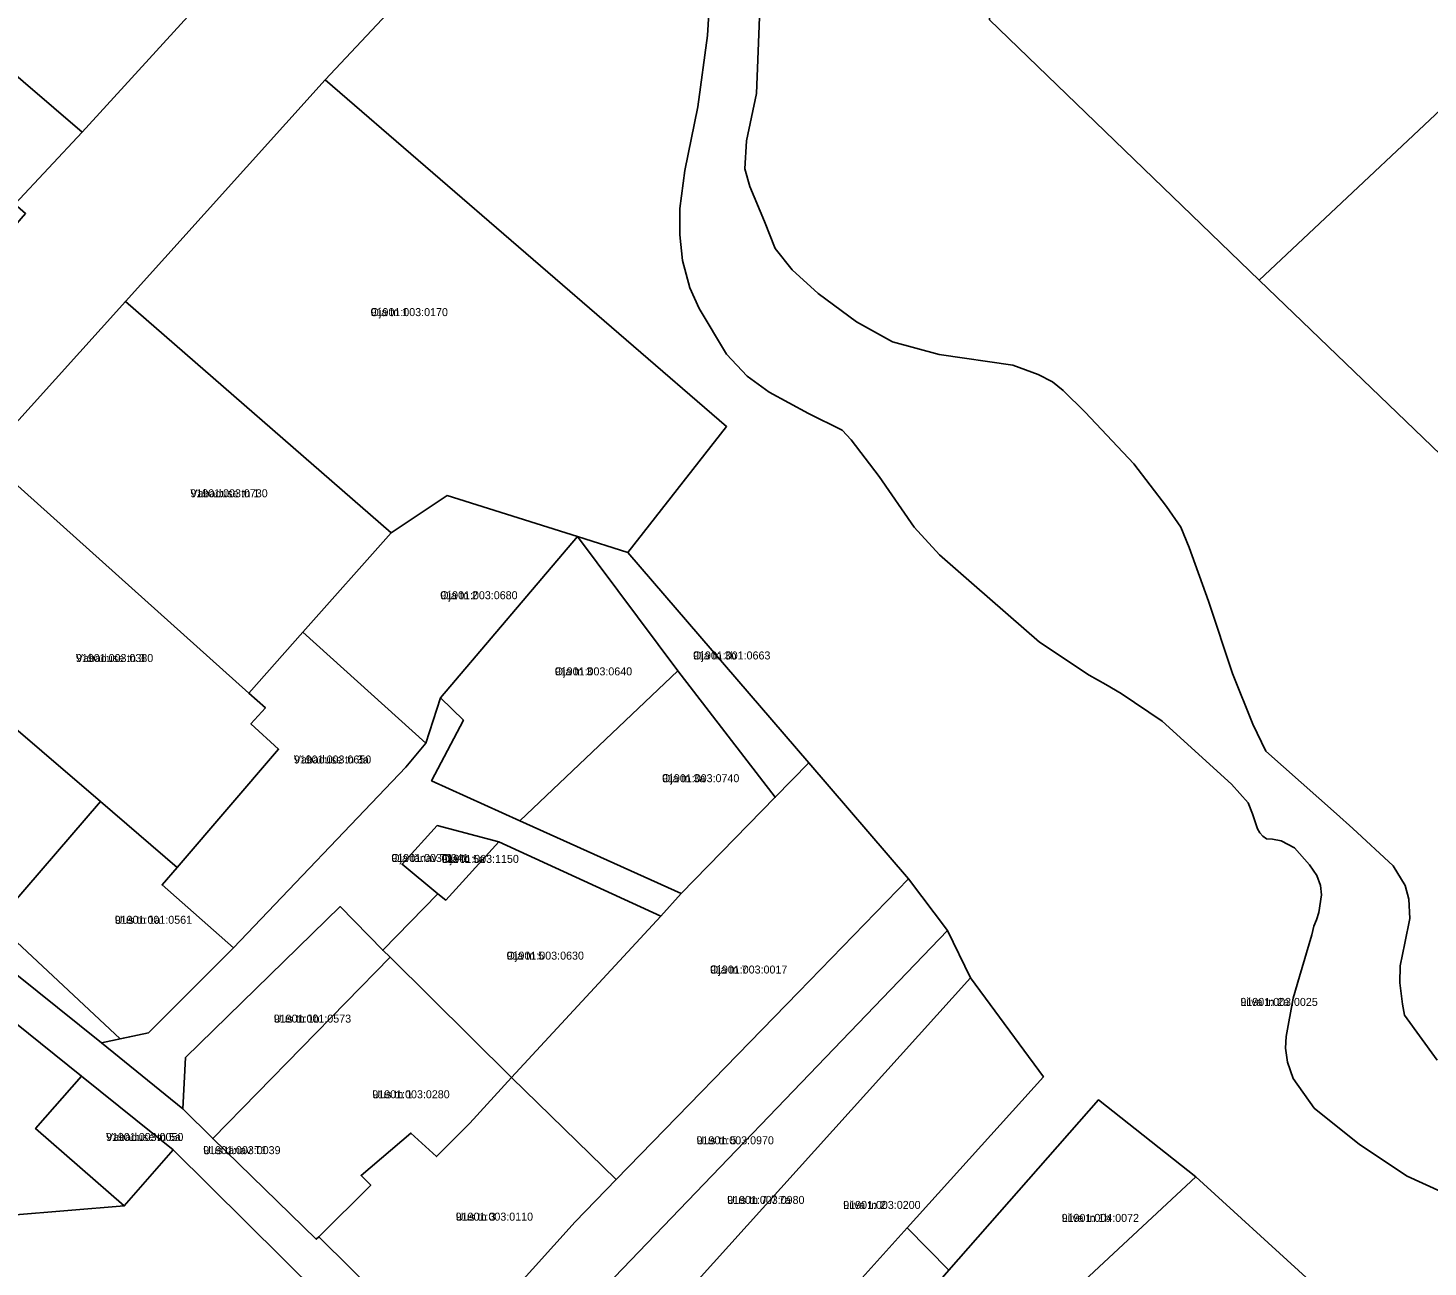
# Model space of a CAD drawing. Extents: x 675810 to 681273, y 6411190 to 6417565.
# Drawn here: x 678158 to 678420.5, y 6415545.6 to 6415777.9 of the extents above; entities that cross this region are included whole.
import ezdxf

# ---------------------------------------------------------------- set-up
doc = ezdxf.new("R2010")
doc.units = 0
for name, color, linetype in [('L_AADRESS', 7, 'Continuous'), ('PIIR', 7, 'Continuous'), ('TUNNUS', 7, 'Continuous')]:
    doc.layers.add(name, color=color, linetype=linetype)

msp = doc.modelspace()

# ---------------------------------------------------------------- linework, layer by layer
at = {"layer": 'PIIR'}
for points in [[(678311.62, 6415873.73), (678337.22, 6415857.73), (678384.87, 6415828.01), (678435.23, 6415774.28), (678388.81, 6415730.68), (678338.26, 6415779.49), (678339.12, 6415799.7), (678315.07, 6415820.94), (678315.8, 6415837.86), (678296.88, 6415857.6)], [(678117.15, 6415810.82), (678145.86, 6415788.34), (678140.65, 6415781.96), (678168.13, 6415758.41), (678155.55, 6415744.9), (678142.57, 6415755.89), (678143.29, 6415756.75), (678101.32, 6415792.73), (678105.89, 6415797.97)], [(678169.47, 6415811.87), (678195.91, 6415788.86), (678168.13, 6415758.41), (678140.65, 6415781.96), (678145.86, 6415788.34), (678161.91, 6415807.79), (678164.68, 6415809.53), (678167.52, 6415809.86)], [(678456.74, 6415665.31), (678388.81, 6415730.68), (678435.23, 6415774.28), (678499.72, 6415705.57)], [(678213.72, 6415768.23), (678288.98, 6415703.2), (678270.47, 6415679.59), (678261.01, 6415682.57), (678236.61, 6415690.25), (678226.09, 6415683.28), (678176.25, 6415726.67)], [(678149.93, 6415697.54), (678176.25, 6415726.67), (678226.09, 6415683.28), (678209.55, 6415664.67), (678199.42, 6415653.2)], [(678149.93, 6415697.54), (678199.42, 6415653.2), (678202.51, 6415650.44), (678199.77, 6415647.44), (678204.98, 6415642.68), (678185.94, 6415620.54), (678171.56, 6415632.89), (678127.06, 6415671.02)], [(678232.55, 6415643.83), (678209.55, 6415664.67), (678226.09, 6415683.28), (678236.61, 6415690.25), (678261.01, 6415682.57), (678235.3, 6415652.34)], [(678233.67, 6415636.79), (678239.64, 6415648.13), (678235.3, 6415652.34), (678261.01, 6415682.57), (678279.84, 6415657.38), (678250.19, 6415629.29)], [(678304.36, 6415640.15), (678298.08, 6415633.7), (678279.84, 6415657.38), (678261.01, 6415682.57), (678270.47, 6415679.59)], [(678127.06, 6415671.02), (678171.56, 6415632.89), (678151.99, 6415610.15), (678107.63, 6415648.47)], [(678204.98, 6415642.68), (678199.77, 6415647.44), (678202.51, 6415650.44), (678199.42, 6415653.2), (678209.55, 6415664.67), (678232.55, 6415643.83), (678228.86, 6415639.33), (678196.51, 6415605.43), (678183.14, 6415617.25), (678185.94, 6415620.54)], [(678250.19, 6415629.29), (678279.84, 6415657.38), (678298.08, 6415633.7), (678280.46, 6415615.64)], [(678235.3, 6415652.34), (678239.64, 6415648.13), (678233.67, 6415636.79), (678250.19, 6415629.29), (678280.46, 6415615.64), (678276.63, 6415611.39), (678246.29, 6415625.32), (678234.68, 6415628.36), (678228.12, 6415621.13), (678234.8, 6415615.58), (678224.49, 6415604.99), (678216.52, 6415613.17), (678187.5, 6415584.87), (678186.99, 6415575.28), (678171.75, 6415587.65), (678180.57, 6415589.51), (678196.51, 6415605.43), (678228.86, 6415639.33), (678232.55, 6415643.83)], [(678107.63, 6415648.47), (678151.99, 6415610.15), (678175.26, 6415588.39), (678171.75, 6415587.65), (678102.82, 6415642.96)], [(678098.17, 6415637.56), (678102.82, 6415642.96), (678171.75, 6415587.65), (678186.99, 6415575.28), (678192.63, 6415569.68), (678212.04, 6415550.8), (678212.55, 6415551.27), (678236.61, 6415527.43), (678236.29, 6415527.07), (678244.28, 6415519.15), (678243.42, 6415518.28), (678252.93, 6415507.94), (678255.14, 6415506.85), (678268.24, 6415492.75), (678265.34, 6415490.55), (678245.76, 6415508.69), (678229.11, 6415524.4), (678212.62, 6415540.4), (678185.22, 6415567.57), (678168, 6415581.41), (678135.27, 6415607.73)], [(678304.36, 6415640.15), (678323.09, 6415618.36), (678302.46, 6415597.15), (678268.24, 6415562), (678248.62, 6415581.15), (678276.63, 6415611.39), (678280.46, 6415615.64), (678298.08, 6415633.7)], [(678180.57, 6415589.51), (678175.26, 6415588.39), (678151.99, 6415610.15), (678171.56, 6415632.89), (678185.94, 6415620.54), (678183.14, 6415617.25), (678196.51, 6415605.43)], [(678246.29, 6415625.32), (678236.32, 6415614.4), (678234.8, 6415615.58), (678228.12, 6415621.13), (678234.68, 6415628.36)], [(678225.92, 6415603.68), (678224.49, 6415604.99), (678234.8, 6415615.58), (678236.32, 6415614.4), (678246.29, 6415625.32), (678276.63, 6415611.39), (678248.62, 6415581.15)], [(678260.59, 6415554.09), (678268.24, 6415562), (678302.46, 6415597.15), (678323.09, 6415618.36), (678330.39, 6415608.7), (678258.82, 6415534.18), (678255.99, 6415536.99), (678249.4, 6415530.35), (678252.42, 6415527.35), (678244.28, 6415519.15), (678236.29, 6415527.07), (678236.61, 6415527.43)], [(678225.92, 6415603.68), (678192.63, 6415569.68), (678186.99, 6415575.28), (678187.5, 6415584.87), (678216.52, 6415613.17), (678224.49, 6415604.99)], [(678106.73, 6415576.96), (678116.66, 6415587.67), (678135.27, 6415607.73), (678168, 6415581.41), (678159.4, 6415571.56), (678176.04, 6415557.04), (678133.69, 6415553.59), (678122.65, 6415563.18)], [(678252.93, 6415507.94), (678243.42, 6415518.28), (678244.28, 6415519.15), (678252.42, 6415527.35), (678249.4, 6415530.35), (678255.99, 6415536.99), (678258.82, 6415534.18), (678330.39, 6415608.7), (678334.71, 6415599.8), (678273.32, 6415531.74), (678258.97, 6415517.14), (678261.93, 6415513.65), (678255.14, 6415506.85)], [(678225.92, 6415603.68), (678248.62, 6415581.15), (678240.82, 6415572.58), (678234.57, 6415566.31), (678229.77, 6415570.7), (678220.45, 6415562.77), (678222.25, 6415560.93), (678212.55, 6415551.27), (678212.04, 6415550.8), (678192.63, 6415569.68)], [(678289.62, 6415516.07), (678277.75, 6415527.48), (678273.32, 6415531.74), (678334.71, 6415599.8), (678348.36, 6415581.27), (678322.83, 6415552.96)], [(678185.22, 6415567.57), (678176.04, 6415557.04), (678159.4, 6415571.56), (678168, 6415581.41)], [(678222.25, 6415560.93), (678220.45, 6415562.77), (678229.77, 6415570.7), (678234.57, 6415566.31), (678240.82, 6415572.58), (678248.62, 6415581.15), (678268.24, 6415562), (678260.59, 6415554.09), (678236.61, 6415527.43), (678212.55, 6415551.27)], [(678358.7, 6415576.94), (678376.95, 6415562.53), (678339.73, 6415527.8), (678326.62, 6415540.38), (678330.66, 6415545.02)], [(678289.51, 6415473.6), (678287.12, 6415475.58), (678308.15, 6415496.68), (678334.02, 6415522.41), (678339.73, 6415527.8), (678376.95, 6415562.53), (678397.66, 6415543.62), (678386.72, 6415533.35), (678320.47, 6415471.09), (678305.14, 6415487.16), (678299.48, 6415482.33)], [(678322.83, 6415552.96), (678330.66, 6415545.02), (678326.62, 6415540.38), (678339.73, 6415527.8), (678334.02, 6415522.41), (678322.24, 6415535.22), (678297.78, 6415506.92), (678277.87, 6415483.96), (678273.27, 6415478.75), (678267.51, 6415471.9), (678256.4, 6415458.9), (678239.98, 6415439.6), (678219.73, 6415415.84), (678209.19, 6415425.16), (678222.13, 6415440.3), (678237.88, 6415458.68), (678250.46, 6415473.29), (678265.34, 6415490.55), (678268.24, 6415492.75), (678278.92, 6415504.59), (678289.62, 6415516.07)]]:
    msp.add_lwpolyline(points, close=True, dxfattribs=at)
for points in [[(678276.58, 6415835.21), (678213.72, 6415768.23), (678176.25, 6415726.67), (678149.93, 6415697.54), (678127.06, 6415671.02), (678107.63, 6415648.47), (678102.82, 6415642.96), (678098.17, 6415637.56), (678081.44, 6415618.31), (678059.53, 6415593.19), (678039.87, 6415570.55), (678019.75, 6415586.05), (678026.78, 6415586.06), (678056.29, 6415620.89), (678082.36, 6415651.31), (678094.05, 6415664.94), (678127.15, 6415703.55), (678137.13, 6415719.66), (678157.55, 6415743.14), (678155.55, 6415744.9), (678168.13, 6415758.41), (678195.91, 6415788.86)], [(678434.11, 6415497.88), (678402.16, 6415516.32), (678386.72, 6415533.35), (678397.66, 6415543.62), (678376.95, 6415562.53), (678358.7, 6415576.94), (678330.66, 6415545.02), (678322.83, 6415552.96), (678348.36, 6415581.27), (678334.71, 6415599.8), (678330.39, 6415608.7), (678323.09, 6415618.36), (678304.36, 6415640.15), (678270.47, 6415679.59), (678288.98, 6415703.2), (678213.72, 6415768.23), (678276.58, 6415835.21)], [(678422.19, 6415584.38), (678416.07, 6415592.85), (678415.7, 6415594.91), (678415.22, 6415598.88), (678415.27, 6415602.06), (678416.12, 6415606.34), (678417.07, 6415610.95), (678416.86, 6415614.6), (678416.22, 6415617.14), (678413.96, 6415620.8), (678406.37, 6415627.81), (678403.35, 6415630.6), (678390.05, 6415642.3), (678387.61, 6415647.4), (678383.8, 6415656.92), (678379.32, 6415670.43), (678375.7, 6415680.54), (678374.12, 6415684.34), (678371.45, 6415688.18), (678365.31, 6415696.21), (678356.18, 6415705.9), (678352.07, 6415709.94), (678350.09, 6415711.59), (678347.37, 6415712.96), (678342.63, 6415714.71), (678328.85, 6415716.7), (678320.05, 6415719.08), (678313.32, 6415722.83), (678306.12, 6415728.18), (678301.28, 6415732.61), (678298.1, 6415736.6), (678296.07, 6415741.66), (678293.34, 6415748.23), (678292.42, 6415751.54), (678292.69, 6415756.8), (678294.57, 6415765.66), (678296.23, 6415807.05)], [(678296.23, 6415807.05), (678294.57, 6415765.66), (678292.69, 6415756.8), (678292.42, 6415751.54), (678293.34, 6415748.23), (678296.07, 6415741.66), (678298.1, 6415736.6), (678301.28, 6415732.61), (678306.12, 6415728.18), (678313.32, 6415722.83), (678320.05, 6415719.08), (678328.85, 6415716.7), (678342.63, 6415714.71), (678347.37, 6415712.96), (678350.09, 6415711.59), (678352.07, 6415709.94), (678356.18, 6415705.9), (678365.31, 6415696.21), (678371.45, 6415688.18), (678374.12, 6415684.34), (678375.7, 6415680.54), (678379.32, 6415670.43), (678383.8, 6415656.92), (678387.61, 6415647.4), (678390.05, 6415642.3), (678403.35, 6415630.6), (678406.37, 6415627.81), (678413.96, 6415620.8), (678416.22, 6415617.14), (678416.86, 6415614.6), (678417.07, 6415610.95), (678416.12, 6415606.34), (678415.27, 6415602.06), (678415.22, 6415598.88), (678415.7, 6415594.91), (678416.07, 6415592.85), (678422.19, 6415584.38)], [(678287.07, 6415804.54), (678285.39, 6415776.54), (678283.56, 6415763.15), (678281.15, 6415751.2), (678280.23, 6415744.12), (678280.18, 6415739.15), (678280.7, 6415734.34), (678282.08, 6415729.22), (678283.83, 6415725.32), (678288.95, 6415716.8), (678292.83, 6415712.67), (678296.98, 6415709.65), (678304.31, 6415705.66), (678310.65, 6415702.5), (678312.3, 6415700.74), (678317.56, 6415693.82), (678324.15, 6415684.36), (678328.89, 6415679.12), (678335.38, 6415673.44), (678347.63, 6415662.75), (678356.92, 6415656.61), (678360.08, 6415654.8), (678362.95, 6415653.16), (678370.65, 6415647.96), (678383.61, 6415636.11), (678386.77, 6415632.64), (678387.57, 6415630.58), (678388.52, 6415627.76), (678388.97, 6415626.99), (678389.5, 6415626.41), (678390.23, 6415625.9), (678391.34, 6415625.82), (678392.97, 6415625.54), (678395.45, 6415624.18), (678398.27, 6415621), (678399.66, 6415619.02), (678400.3, 6415617.11), (678400.5, 6415615.37), (678400.04, 6415612.08), (678399.57, 6415610.69), (678399.05, 6415609.5), (678398.7, 6415607.91), (678396.36, 6415600.05), (678395.17, 6415596.04), (678393.86, 6415588.82), (678393.74, 6415586.64), (678394.14, 6415584.02), (678395.19, 6415580.96), (678399.15, 6415575.36), (678407.64, 6415568.6), (678416.57, 6415562.63), (678423.02, 6415559.69)], [(678423.02, 6415559.69), (678416.57, 6415562.63), (678407.64, 6415568.6), (678399.15, 6415575.36), (678395.19, 6415580.96), (678394.14, 6415584.02), (678393.74, 6415586.64), (678393.86, 6415588.82), (678395.17, 6415596.04), (678396.36, 6415600.05), (678398.7, 6415607.91), (678399.05, 6415609.5), (678399.57, 6415610.69), (678400.04, 6415612.08), (678400.5, 6415615.37), (678400.3, 6415617.11), (678399.66, 6415619.02), (678398.27, 6415621), (678395.45, 6415624.18), (678392.97, 6415625.54), (678391.34, 6415625.82), (678390.23, 6415625.9), (678389.5, 6415626.41), (678388.97, 6415626.99), (678388.52, 6415627.76), (678387.57, 6415630.58), (678386.77, 6415632.64), (678383.61, 6415636.11), (678370.65, 6415647.96), (678362.95, 6415653.16), (678360.08, 6415654.8), (678356.92, 6415656.61), (678347.63, 6415662.75), (678335.38, 6415673.44), (678328.89, 6415679.12), (678324.15, 6415684.36), (678317.56, 6415693.82), (678312.3, 6415700.74), (678310.65, 6415702.5), (678304.31, 6415705.66), (678296.98, 6415709.65), (678292.83, 6415712.67), (678288.95, 6415716.8), (678283.83, 6415725.32), (678282.08, 6415729.22), (678280.7, 6415734.34), (678280.18, 6415739.15), (678280.23, 6415744.12), (678281.15, 6415751.2), (678283.56, 6415763.15), (678285.39, 6415776.54), (678287.07, 6415804.54)], [(678338.26, 6415779.49), (678388.81, 6415730.68), (678456.74, 6415665.31)], [(678133.69, 6415553.59), (678176.04, 6415557.04), (678185.22, 6415567.57), (678212.62, 6415540.4), (678192.24, 6415514.99), (678207.91, 6415500.54), (678214.36, 6415494.68), (678201.34, 6415479.3), (678204.55, 6415476.57), (678193.95, 6415464.45), (678180.75, 6415449.2), (678176.17, 6415453.14), (678188.52, 6415467.41), (678186.61, 6415469.04), (678175.08, 6415479.02), (678159.11, 6415492.87), (678146.81, 6415478.68)]]:
    msp.add_lwpolyline(points, dxfattribs=at)

# ---------------------------------------------------------------- texts
at = {"layer": 'L_AADRESS'}
for s, p in [('Oja tn 1', (678222.22, 6415723.91)), ('Vabaduse tn 1', (678188.43, 6415689.94)), ('Oja tn 2', (678235.28, 6415670.82)), ('Vabaduse tn 3', (678166.97, 6415659.04)), ('Oja tn 3b', (678282.68, 6415659.53)), ('Oja tn 3', (678256.76, 6415656.54)), ('Vabaduse tn 3a', (678207.84, 6415640.02)), ('Oja tn 3a', (678276.86, 6415636.51)), ('Oja tänav T1', (678226.11, 6415621.55)), ('Oja tn 5a', (678235.52, 6415621.38)), ('Uus tn 1a', (678174.25, 6415609.96)), ('Oja tn 5', (678247.72, 6415603.24)), ('Oja tn 7', (678285.86, 6415600.63)), ('Liiva tn 2a', (678385.31, 6415594.56)), ('Uus tn 1b', (678204.07, 6415591.43)), ('Uus tn 1', (678222.55, 6415577.24)), ('Vabaduse tn 5a', (678172.62, 6415569.23)), ('Uus tänav T1', (678190.84, 6415566.76)), ('Uus tn 5', (678283.34, 6415568.61)), ('Uus tn 7 // 7a', (678289.07, 6415557.43)), ('Liiva tn 2', (678310.84, 6415556.49)), ('Uus tn 3', (678238.18, 6415554.29)), ('Liiva tn 1b', (678351.79, 6415554.06))]:
    msp.add_text(s, height=1.5, dxfattribs=at).set_placement(p)
at = {"layer": 'TUNNUS'}
for s, p in [('91901:003:0170', (678222.22, 6415723.91)), ('91901:003:0730', (678188.43, 6415689.94)), ('91901:003:0680', (678235.28, 6415670.82)), ('91901:003:0380', (678166.97, 6415659.04)), ('91901:001:0663', (678282.68, 6415659.53)), ('91901:003:0640', (678256.76, 6415656.54)), ('91901:003:0650', (678207.84, 6415640.02)), ('91901:003:0740', (678276.86, 6415636.51)), ('91901:003:0041', (678226.11, 6415621.55)), ('91901:003:1150', (678235.52, 6415621.38)), ('91901:001:0561', (678174.25, 6415609.96)), ('91901:003:0630', (678247.72, 6415603.24)), ('91901:003:0017', (678285.86, 6415600.63)), ('91901:003:0025', (678385.31, 6415594.56)), ('91901:001:0573', (678204.07, 6415591.43)), ('91901:003:0280', (678222.55, 6415577.24)), ('91901:003:0050', (678172.62, 6415569.23)), ('91901:003:0039', (678190.84, 6415566.76)), ('91901:003:0970', (678283.34, 6415568.61)), ('91901:003:0980', (678289.07, 6415557.43)), ('91901:003:0200', (678310.84, 6415556.49)), ('91901:003:0110', (678238.18, 6415554.29)), ('91901:004:0072', (678351.79, 6415554.06))]:
    msp.add_text(s, height=1.5, dxfattribs=at).set_placement(p)

doc.saveas('drawing.dxf')
